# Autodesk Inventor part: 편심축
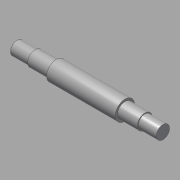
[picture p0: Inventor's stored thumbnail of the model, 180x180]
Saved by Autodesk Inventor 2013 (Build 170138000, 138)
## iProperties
Created: 2015-10
Part Number: 편심축
Document SubType Name: Modeling
Designer: mdu
Density: 7.86 g/cm^3
Material: 강철, 연강
Mass: 1163.82 g
Surface Area: 210.981 cm^2
Volume: 148.069 cm^3
Author: mdu
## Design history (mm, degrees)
sketch "스케치1"
  geometry: L1 (-20.5, -41.331)-(-20.5, 32.669) reference; L2 (7.5, -30.031)-(7.5, 21.369) reference; L3 (135.5, -30.331)-(135.5, 21.669) reference; L4 (121.5, 21.369)-(121.5, -30.031) reference; L5 (184.5, -4.331)-(-7.5, -4.331); L6 (184.5, -4.331)-(184.5, 6.669); L7 (154.5, 8.169)-(121.5, 8.169); L8 (121.5, 8.169)-(121.5, 11.669); L9 (121.5, 11.669)-(7.5, 11.669); L10 (7.5, 11.669)-(7.5, 8.169); L11 (7.5, 8.169)-(-7.5, 8.169); L12 (-7.5, 8.169)-(-7.5, -4.331); L13 (154.5, 8.169)-(154.5, 6.669); L14 (154.5, 6.669)-(184.5, 6.669); C1 r 32.5 at (64.5, -4.331) reference; 1 further point
  constraints: 21 end point, 8 perpendicular, 5 point on line, 1 collinear
  dimensions: "d1" = 25 diameter of L11 L5; "d2" = 32 diameter of L9 L5; "d4" = 15 distance of L10.end L11.end; "d15" = 33 distance of L7.start L7.end; "d26" = 30 distance of L13.end L6.end; "d36" = 22 diameter of L14 L5
revolve "회전1" sketch "스케치1" stored, may be unused: angle "d6" = 90 deg
node "작업 평면1"
sketch "스케치2"
  geometry: C1 r 16 at (0, 0) reference; C2 r 20.75 at (0, 4)
  constraints: 1 centre point, 1 vertical alignment
  dimensions: "d34" = 4 distance of C2.centre C1.centre; "d35" = 41.5 diameter of C2
extrude "돌출1" join sketch "스케치2" stored distance "d9" = 40; taper "d10" = 0 deg
chamfer "모따기1" distance "d11" = 1; stored, may be unused: second distance "d12" = 2, angle "d13" = 45 deg
node "작업 평면2"
sketch "스케치3"
  geometry: L1 (-15, -10)-(-15, 10) reference; L2 (-15, 3)-(0, 3); L3 (0, -3)-(-15, -3); A1 r 3 centre (0, 0) between (0, -3) and (0, 3); 2 further points
  constraints: 4 end point, 2 perpendicular, 2 point on circle, 2 point on line, 2 tangent, 1 centre point, 1 horizontal alignment, 1 midpoint
  dimensions: "d16" = 18 dimension on A1 L1; "d17" = 6 distance between parallel lines of L3 L2
extrude "돌출2" cut sketch "스케치3" distance "d18" = 3.5; taper "d19" = 0 deg
node "솔리드1"
node "참조1"
node "참조2"
node "참조3"
node "참조4"
node "참조5"
other parameters: "d30" = 35
